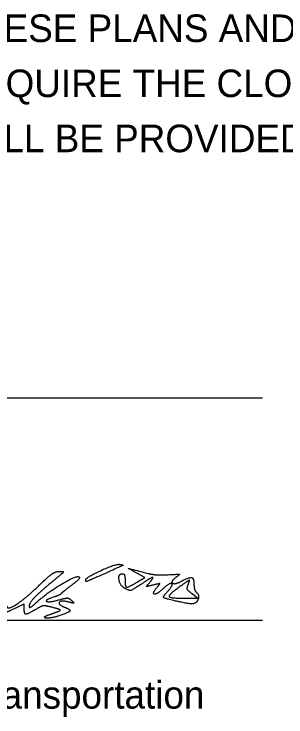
# Model space of a CAD drawing. Extents: x 0 to 34, y 0 to 22.
# Drawn here: x 26.766 to 28.147, y 7.305 to 10.877 of the extents above; entities that cross this region are included whole.
import ezdxf

# ---------------------------------------------------------------- set-up
doc = ezdxf.new("R2010")
doc.units = 0
doc.layers.add('SH_Data', color=7, linetype='Continuous')
doc.layers.add('SH_Text', color=7, linetype='Continuous')

msp = doc.modelspace()

# ---------------------------------------------------------------- linework, layer by layer
at = {"layer": 'SH_Data'}
for p, q in [((24.5279, 8.9262), (28.0279, 8.9262)), ((24.5279, 7.7968), (28.0279, 7.7968))]:
    msp.add_line(p, q, dxfattribs=at)
at = {"layer": 'SH_Text'}
for p, q in [((27.1295, 8.001), (27.1295, 8.001)), ((27.582, 7.8948), (27.582, 7.8948))]:
    msp.add_line(p, q, dxfattribs=at)
for points in [[(27.3933, 7.9914), (27.4297, 8.0129), (27.3889, 8.0359)], [(27.642, 7.9079), (27.6982, 7.908), (27.6695, 7.9301)]]:
    msp.add_lwpolyline(points, dxfattribs=at)
for points in [[(27.1295, 8.001), (27.1295, 8.0134), (27.2823, 8.0837), (27.3012, 8.08)], [(27.3012, 8.08), (27.3219, 8.076), (27.3226, 8.0764), (27.201, 8.0218)], [(26.8951, 7.9753), (26.9403, 8.019), (26.9774, 8.0447), (26.9951, 8.0444)], [(26.9951, 8.0444), (27.0194, 8.0439), (27.0156, 8.0375), (26.967, 7.9975)], [(27.3889, 8.0359), (27.3461, 8.06), (27.3452, 8.06), (27.4482, 8.0336)], [(26.8763, 7.8841), (26.93, 7.9329), (27.0769, 8.0229), (27.0938, 8.0172)], [(27.0938, 8.0172), (27.1022, 8.0144), (27.087, 7.9957), (27.0599, 7.9755)], [(27.201, 8.0218), (27.1385, 7.9937), (27.1295, 7.9911), (27.1295, 8.001)], [(27.3305, 7.9569), (27.304, 7.9711), (27.293, 8.0324), (27.317, 8.0324)], [(27.317, 8.0324), (27.3238, 8.0324), (27.3295, 8.0184), (27.3295, 8.0012)], [(27.4529, 7.9866), (27.4773, 8.0162), (27.4615, 8.0124), (27.4052, 7.9752)], [(27.4482, 8.0336), (27.4688, 8.0284), (27.5138, 8.0256), (27.5482, 8.0275)], [(27.5482, 8.0275), (27.6031, 8.0306), (27.608, 8.029), (27.5881, 8.0142)], [(27.5881, 8.0142), (27.5593, 7.9927), (27.5822, 7.9763), (27.6159, 7.9944)], [(27.6159, 7.9944), (27.6561, 8.0159), (27.6795, 8.0101), (27.6795, 7.9787)], [(26.7295, 7.8684), (26.7295, 7.8456), (26.8248, 7.907), (26.8951, 7.9753)], [(26.967, 7.9975), (26.8929, 7.9366), (26.842, 7.883), (26.842, 7.8663)], [(27.0599, 7.9755), (27.0328, 7.9553), (27.0079, 7.9353), (27.0045, 7.9311)], [(27.3295, 8.0012), (27.3295, 7.9644), (27.3438, 7.9622), (27.3933, 7.9914)], [(27.4052, 7.9752), (27.3652, 7.9487), (27.3519, 7.9454), (27.3305, 7.9569)], [(27.4723, 7.9749), (27.4392, 7.9667), (27.4374, 7.9678), (27.4529, 7.9866)], [(27.4924, 7.9642), (27.507, 7.9818), (27.5047, 7.983), (27.4723, 7.9749)], [(27.5462, 7.9428), (27.5767, 7.9764), (27.5551, 7.9874), (27.5211, 7.9554)], [(27.6497, 7.9756), (27.6596, 8.0014), (27.6514, 7.9983), (27.5888, 7.9527)], [(27.6695, 7.9301), (27.6491, 7.9458), (27.6434, 7.959), (27.6497, 7.9756)], [(27.6795, 7.9787), (27.6795, 7.9629), (27.6858, 7.9436), (27.6936, 7.9358)], [(27.0045, 7.9311), (27.001, 7.9268), (26.9856, 7.9194), (26.9701, 7.9145)], [(27.5211, 7.9554), (27.4892, 7.9255), (27.4661, 7.9325), (27.4924, 7.9642)], [(27.582, 7.8948), (27.5272, 7.9077), (27.5215, 7.9154), (27.5462, 7.9428)], [(27.5888, 7.9527), (27.5461, 7.9217), (27.5626, 7.9078), (27.642, 7.9079)], [(27.6936, 7.9358), (27.7014, 7.928), (27.7044, 7.9128), (27.7003, 7.902)], [(26.9701, 7.9145), (26.9206, 7.8991), (26.9401, 7.8854), (26.9919, 7.8992)], [(26.9919, 7.8992), (27.0302, 7.9095), (27.0455, 7.9089), (27.0575, 7.8966)], [(27.0575, 7.8966), (27.0702, 7.8837), (27.0666, 7.8823), (27.0388, 7.8892)], [(27.7003, 7.902), (27.6922, 7.8809), (27.651, 7.8784), (27.582, 7.8948)], [(26.817, 7.8559), (26.817, 7.8788), (26.8159, 7.8788), (26.7698, 7.8559)], [(26.842, 7.8663), (26.842, 7.8588), (26.8574, 7.8668), (26.8763, 7.8841)], [(26.9621, 7.8609), (26.9233, 7.8708), (26.9065, 7.8691), (26.8789, 7.8528)], [(26.992, 7.8417), (27.0034, 7.8458), (26.9917, 7.8533), (26.9621, 7.8609)], [(27.0388, 7.8892), (27.0021, 7.8982), (26.9889, 7.8751), (27.0232, 7.862)], [(27.0232, 7.862), (27.0538, 7.8502), (27.0449, 7.8353), (26.9981, 7.8199)], [(26.7698, 7.8559), (26.7324, 7.8374), (26.7138, 7.8351), (26.6807, 7.8446)], [(26.8789, 7.8528), (26.8339, 7.8262), (26.817, 7.8271), (26.817, 7.8559)], [(26.9981, 7.8199), (26.9515, 7.8045), (26.9042, 7.8102), (26.9482, 7.8259)], [(26.9482, 7.8259), (26.962, 7.8308), (26.9817, 7.8379), (26.992, 7.8417)]]:
    msp.add_open_spline(points, degree=2, dxfattribs=at)

# ---------------------------------------------------------------- texts
at = {"layer": 'SH_Data'}
for s, p in [(' I HEREBY APPROVE THESE PLANS AND DECLARE THAT THE MAKING OF THIS', (24.5279, 10.735)), ('IMPROVEMENT WILL REQUIRE THE CLOSING TO TRAFFIC OF THE HIGHWAY', (24.5279, 10.455)), ('AND THAT DETOURS WILL BE PROVIDED AS INDICATED ON SHEET 4.', (24.5279, 10.175))]:
    msp.add_text(s, height=0.14, dxfattribs=at).set_placement(p)
at = {"layer": 'SH_Text'}
msp.add_text('Director, Department of Transportation', height=0.14, dxfattribs=at).set_placement((24.5279, 7.3468))

doc.saveas('drawing.dxf')
